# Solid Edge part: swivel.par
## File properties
Title: Swivel
Author: Deepak Maini
Template: normal.par
Last saved by: CADCIM
Revision: 12
Application: Solid Edge
Density: 0.0000078 kg/mm^3
Accuracy: 0.01
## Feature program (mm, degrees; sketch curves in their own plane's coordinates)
sketch for "unnamed RevolvedProtrusion 1" plane through (0, 0, -25.4) normal (0, 0, 1) x-axis (1, 0, 0)
revolve "unnamed RevolvedProtrusion 1" add finite 360 deg about sketch line (-85.0097, -12.7562) -> (-3.81, -12.7562)
sketch for "unnamed RevolvedProtrusion 2" plane through (0, -12.7, 0) normal (0, -1, 0) x-axis (1, 0, 0)
revolve "unnamed RevolvedProtrusion 2" add full turn 360 deg about sketch line (-44.45, 28.0428) -> (-44.45, -71.2043)
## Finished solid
Body 1: solid body, 14 faces, 13 edges, 0 vertices.
  Faces by surface: plane 8, cylinder 6
  Edges by curve: circle 12, intersection 1
Bounding box of the edges (mm): 81.200 x 25.456 x 81.280, from (-85.0097, -25.4562, -66.04) to (-3.81, 0, 15.24).
Cylindrical faces by radius (mm): R6.35 x4, R12.7 x2
Planar faces by outward normal: +x 2, +z 2, -x 2, -z 2
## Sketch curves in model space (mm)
line (-85.0097, -12.7562, -25.4) -> (-3.81, -12.7562, -25.4)
line (-85.0097, -19.1062, -25.4) -> (-85.0097, -12.7562, -25.4)
line (-85.0097, -19.1062, -25.4) -> (-69.7697, -19.1062, -25.4)
line (-69.7697, -19.1062, -25.4) -> (-69.7697, -25.4562, -25.4)
line (-69.7697, -25.4562, -25.4) -> (-19.05, -25.4562, -25.4)
line (-19.05, -25.4562, -25.4) -> (-19.05, -19.1062, -25.4)
line (-19.05, -19.1062, -25.4) -> (-3.81, -19.1062, -25.4)
line (-3.81, -19.1062, -25.4) -> (-3.81, -12.7562, -25.4)
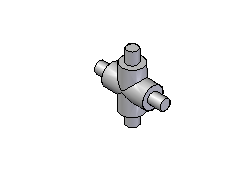
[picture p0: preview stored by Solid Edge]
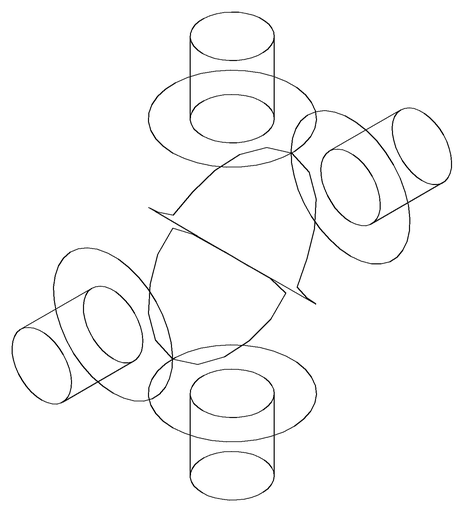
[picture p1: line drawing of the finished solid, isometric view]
